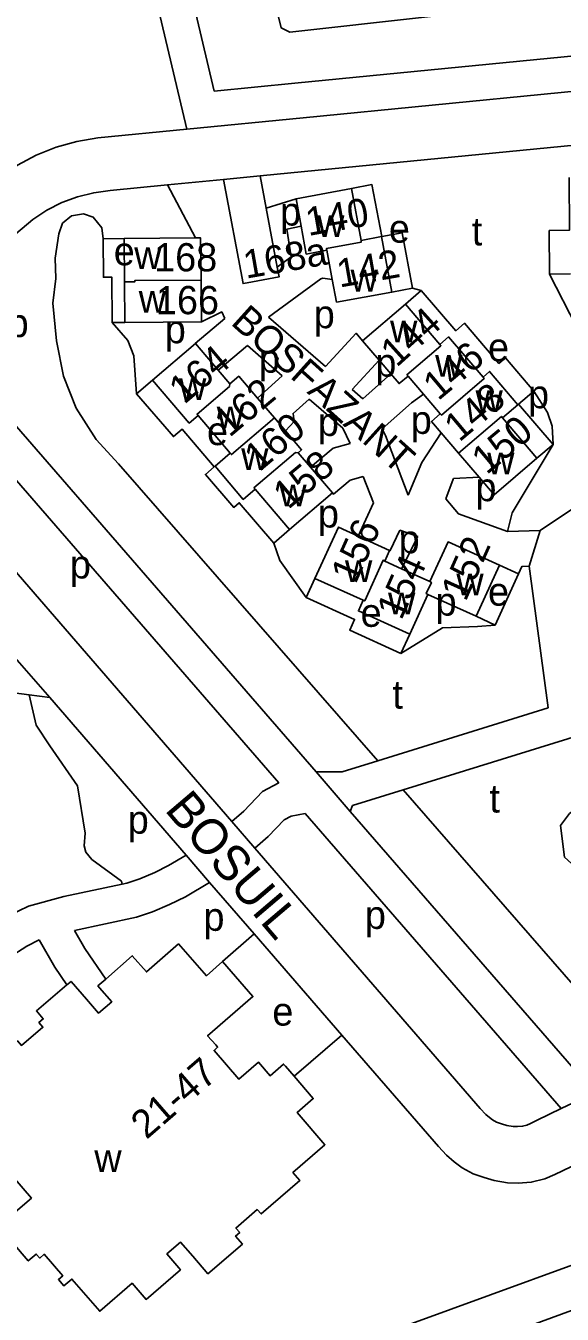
# Model space of a CAD drawing. Extents: x 155854 to 157362, y 383621 to 384685.
# Drawn here: x 156844.9 to 156920.8, y 383747.7 to 383930.2 of the extents above; entities that cross this region are included whole.
import ezdxf

# ---------------------------------------------------------------- set-up
doc = ezdxf.new("R2010")
doc.units = 0
for name, color, linetype in [('BLT_Basislijn', 7, 'Continuous'), ('BLT_Bebouwing', 7, 'Continuous'), ('BLT_Centroide', 7, 'Continuous'), ('BLT_Huisnummer', 7, 'Continuous'), ('BLT_Huisnummer_reeks', 7, 'Continuous'), ('BLT_Huisnummer_zonder_bebouwing', 7, 'Continuous'), ('BLT_Onderverdeling_panden', 7, 'Continuous'), ('BLT_Straatnaam', 7, 'Continuous'), ('BLT_Straatnaam_verkleind', 7, 'Continuous'), ('BLT_Vlakafsluiter', 7, 'Continuous')]:
    doc.layers.add(name, color=color, linetype=linetype)

msp = doc.modelspace()

# ---------------------------------------------------------------- linework, layer by layer
at = {"layer": 'BLT_Basislijn'}
for p, q in [((156831.19, 384070.4), (156867.7, 383915.55)), ((156928.32, 383913.85), (156878.09, 383908.93)), ((156878.09, 383908.93), (156872.9, 383908.43)), ((156878.94, 383904.37), (156878.09, 383908.93)), ((156864.96, 383907.65), (156856.85, 383906.85)), ((156872.9, 383908.43), (156864.96, 383907.65)), ((156864.96, 383907.65), (156868.93, 383900.13)), ((156883.16, 383905.7), (156878.94, 383904.37)), ((156880.5, 383896.02), (156878.94, 383904.37)), ((156838.28, 383896.36), (156845.93, 383902.77)), ((156858.82, 383900.05), (156855.86, 383900)), ((156919.04, 383895.02), (156922.01, 383895.04)), ((156919.04, 383895.02), (156922.86, 383887.56)), ((156896.7, 383892.48), (156899.63, 383893.03)), ((156900.88, 383892.69), (156898.62, 383890.76)), ((156899.63, 383893.03), (156900.88, 383892.69)), ((156885.98, 383824.5), (156829.83, 383889.28)), ((156879.25, 383888.91), (156887.3, 383881.93)), ((156857.15, 383888.14), (156858.92, 383888.16)), ((156880.7, 383822.96), (156826, 383886.06)), ((156872.14, 383881.4), (156876.27, 383884.88)), ((156876.27, 383884.88), (156881.2, 383880.6)), ((156891.08, 383878.65), (156894.92, 383882.81)), ((156862.86, 383879.99), (156860.6, 383878.06)), ((156881.2, 383880.6), (156877.68, 383877.46)), ((156892.59, 383877.34), (156896.58, 383880.87)), ((156891.08, 383878.65), (156892.59, 383877.34)), ((156917.25, 383868.95), (156919.52, 383870.89)), ((156931.24, 383867.82), (156917.68, 383858.68)), ((156892.67, 383866.36), (156894.11, 383862.61)), ((156894.11, 383862.61), (156891.93, 383857.91)), ((156880, 383856.92), (156882.24, 383858.83)), ((156897.84, 383858.76), (156900.41, 383857.83)), ((156900.41, 383857.83), (156898.1, 383853.28)), ((156913.08, 383858.54), (156917.68, 383858.68)), ((156911.35, 383845.3), (156914.64, 383852.55)), ((156914.64, 383852.55), (156911.93, 383853.78)), ((156916.12, 383853.63), (156918.83, 383833.56)), ((156885.83, 383851.91), (156884.6, 383849.21)), ((156908.63, 383846.54), (156911.35, 383845.3)), ((156898, 383841.29), (156899.24, 383844)), ((156843.37, 383840.73), (156848.31, 383835.02)), ((156848.31, 383835.02), (156845.38, 383835.41)), ((156848.31, 383835.02), (156867.61, 383812.7)), ((156918.83, 383833.56), (156894.71, 383826.06)), ((156936.17, 383833.7), (156898.3, 383821.94)), ((156874.06, 383817.46), (156877.33, 383813.68)), ((156920.69, 383776.82), (156884.46, 383818.62)), ((156925.36, 383779.07), (156890.83, 383818.91)), ((156867.61, 383812.7), (156870.93, 383808.85)), ((156870.93, 383808.85), (156877.24, 383801.56)), ((156872.76, 383797.63), (156877.24, 383801.56)), ((156877.24, 383801.56), (156889.62, 383787.23)), ((156889.62, 383787.23), (156882.88, 383781.38)), ((156920.69, 383776.82), (156925.36, 383779.07)), ((156786.01, 383698.59), (156938.36, 383754.12))]:
    msp.add_line(p, q, dxfattribs=at)
for points in [[(156861.58, 384009.03), (156851.38, 384006.57), (156871.56, 383920.95)], [(156957.23, 383937.68), (156882.29, 383929.3), (156881.04, 383929.91), (156864.57, 383996.87)], [(156959.19, 383929.54), (156882.96, 383922.07)], [(156957.18, 383924.32), (156884.17, 383917.17)], [(156882.96, 383922.07), (156871.56, 383920.95)], [(156884.17, 383917.17), (156867.7, 383915.55)], [(156841.22, 383908.74), (156843.72, 383910.43), (156846.39, 383911.85), (156849.22, 383912.99), (156852.13, 383913.81), (156855.1, 383914.32)], [(156867.7, 383915.55), (156855.1, 383914.32)], [(156921.79, 383908.72), (156921.85, 383901.22), (156918.99, 383901.19), (156919.04, 383895.02)], [(156845.93, 383902.77), (156847.89, 383904.07), (156850, 383905.14), (156852.23, 383905.97), (156854.53, 383906.55), (156856.85, 383906.85)], [(156872.9, 383908.43), (156875.65, 383893.67), (156876.25, 383893.78)], [(156899.63, 383893.03), (156898.17, 383900.87), (156895.28, 383900.33), (156893.9, 383907.69), (156890.99, 383907.14)], [(156894.71, 383826.06), (156858.02, 383868.14), (156854.85, 383871.57), (156852.03, 383876.04), (156850.25, 383880.56), (156849.27, 383885.57), (156848.76, 383890.92), (156849.14, 383894.37), (156849.08, 383897.28), (156849.57, 383900.72), (156850.12, 383902.21), (156851.4, 383903.29), (156853.08, 383903.56), (156854.46, 383903.06), (156855.67, 383901.55), (156855.86, 383900)], [(156880.5, 383896.02), (156882.45, 383897.44), (156881.86, 383901.39), (156883.88, 383901.79)], [(156855.86, 383900), (156855.9, 383894.57), (156857.1, 383894.58), (156857.15, 383888.14)], [(156876.25, 383893.78), (156880.76, 383894.62), (156880.5, 383896.02)], [(156879.25, 383888.91), (156886.67, 383894.33), (156886.94, 383894.43), (156888.27, 383894.23)], [(156916.81, 383878.43), (156912.79, 383883.14), (156911.87, 383882.36), (156907, 383888.05), (156905.75, 383886.98), (156900.88, 383892.69)], [(156868.91, 383885.17), (156868.89, 383885.2), (156873.06, 383888.72)], [(156869.76, 383888.25), (156872.63, 383889.66), (156873.06, 383888.72)], [(156857.15, 383888.14), (156859.37, 383885.6), (156860.22, 383883.42), (156860.6, 383878.06)], [(156887.3, 383881.93), (156891.65, 383886.63), (156892.56, 383885.56)], [(156821.72, 383882.48), (156821.08, 383881.75), (156820.87, 383880.9), (156820.96, 383879.8), (156821.2, 383879.05), (156821.71, 383878.01), (156874.06, 383817.46)], [(156860.6, 383878.06), (156865.79, 383871.99), (156867.03, 383873.06), (156871.59, 383867.73), (156870.33, 383866.65), (156874.34, 383861.96), (156875.12, 383862.62), (156880, 383856.92)], [(156895.35, 383873.1), (156899.49, 383876.78), (156901.21, 383877.99)], [(156919.52, 383870.89), (156914.65, 383876.58), (156916.81, 383878.43)], [(156916.81, 383878.43), (156918.76, 383875.4), (156919.41, 383873.46), (156919.52, 383870.89)], [(156885.01, 383877.3), (156882.73, 383875.27), (156882.9, 383874.12), (156881.65, 383872.82)], [(156885.01, 383877.3), (156889.77, 383873.17), (156890.79, 383871.03)], [(156895.35, 383873.1), (156895.8, 383872.16), (156899.04, 383863.71)], [(156903.71, 383872.53), (156900.94, 383868.32), (156899.04, 383863.71)], [(156885.2, 383867.66), (156888.4, 383870.34), (156890.79, 383871.03)], [(156919.52, 383870.89), (156913.75, 383861.22), (156913.08, 383858.54)], [(156888.31, 383864.02), (156888.44, 383863.86), (156890.79, 383865.83), (156892.67, 383866.36)], [(156909.06, 383866.26), (156905.45, 383866.07), (156905.38, 383865.97), (156904.34, 383863.17)], [(156904.34, 383863.17), (156906.13, 383861.07), (156913.08, 383858.54)], [(156897.84, 383858.76), (156896.48, 383855.84), (156896.39, 383855.88)], [(156880, 383856.92), (156880.88, 383854.44), (156884.6, 383849.21)], [(156914.64, 383852.55), (156915.12, 383853.6), (156916.12, 383853.63)], [(156884.6, 383849.21), (156891.43, 383846.1), (156890.75, 383844.6), (156898, 383841.29)], [(156898, 383841.29), (156903.9, 383844.9), (156908.85, 383845.11), (156911.35, 383845.3)], [(156845.38, 383835.41), (156841.75, 383835.9), (156838.64, 383834.71), (156835.29, 383832.88), (156833.68, 383831.74), (156832.77, 383830.76), (156832.07, 383829.68), (156831.53, 383828.4), (156830.87, 383825.24)], [(156845.38, 383835.41), (156846.38, 383831.13), (156848.3, 383828.2), (156852.25, 383822.51), (156853.3, 383815.83), (156853.19, 383814.02), (156853.41, 383813.15), (156854.25, 383812.11), (156858.47, 383809), (156858.55, 383808.6)], [(156894.71, 383826.06), (156889.66, 383824.5), (156885.98, 383824.5)], [(156880.7, 383822.96), (156878.39, 383821.72), (156875.76, 383818.95), (156874.06, 383817.46)], [(156898.3, 383821.94), (156891.15, 383819.72), (156890.83, 383818.91)], [(156930.33, 383797.53), (156933.42, 383786.63), (156933.49, 383785.67), (156933.02, 383784.82), (156931.88, 383784.36), (156930.72, 383784.77), (156898.3, 383821.94)], [(156929.31, 383821.54), (156927.43, 383821.08), (156924.6, 383820.45), (156921.87, 383818.62), (156920.58, 383816.92), (156921.16, 383812.41), (156924.11, 383809.75)], [(156884.46, 383818.62), (156882.47, 383818.23), (156881.46, 383817.7), (156879.23, 383815.34), (156877.33, 383813.68)], [(156877.33, 383813.68), (156909.22, 383776.8), (156909.99, 383775.99), (156910.51, 383775.53), (156910.95, 383775.22), (156911.53, 383774.9), (156912.25, 383774.64), (156912.96, 383774.43), (156913.88, 383774.28), (156914.47, 383774.26), (156915.2, 383774.31), (156915.79, 383774.45), (156916.35, 383774.69), (156917.27, 383775.17), (156920.69, 383776.82)], [(156867.61, 383812.7), (156865.11, 383811.22), (156863.17, 383810.26), (156861.03, 383809.36), (156859.22, 383808.74), (156858.55, 383808.6)], [(156858.55, 383808.6), (156850.29, 383806.84), (156845.28, 383805.5), (156842.57, 383804.17), (156839.65, 383802.25), (156835.82, 383799.25), (156833.13, 383796.74)], [(156870.93, 383808.85), (156867.49, 383806.82), (156865.25, 383805.71), (156862.82, 383804.69), (156860.56, 383803.91), (156851.79, 383802.05)], [(156856.22, 383795.15), (156853.26, 383799.48), (156851.79, 383802.05)], [(156846.81, 383800.69), (156845.06, 383799.82), (156842.57, 383798.19), (156839.07, 383795.45), (156836.66, 383793.19), (156835.33, 383791.78), (156834.65, 383790.76), (156834.1, 383789.4), (156832, 383781.21), (156831, 383778.9), (156829.4, 383776.88), (156827.71, 383774.94), (156826.92, 383773.54), (156826.78, 383773.08)], [(156850.73, 383794.32), (156849.02, 383796.82), (156846.81, 383800.69)], [(156889.62, 383787.23), (156903.29, 383771.42), (156904.45, 383770.21), (156905.54, 383769.26), (156906.68, 383768.44), (156908.22, 383767.59), (156909.76, 383767.03), (156911.17, 383766.62), (156913.07, 383766.3), (156914.6, 383766.25), (156916.44, 383766.37), (156918.35, 383766.84)], [(156918.35, 383766.84), (156919.78, 383767.46), (156920.85, 383768.01), (156926.12, 383770.56)], [(156797.74, 383709.25), (156933.44, 383758.72), (156934.4, 383759.51), (156934.72, 383760.23), (156934.34, 383761.07)]]:
    msp.add_lwpolyline(points, dxfattribs=at)
at = {"layer": 'BLT_Bebouwing'}
for p, q in [((156883.16, 383905.7), (156890.99, 383907.14)), ((156890.99, 383907.14), (156892.35, 383899.78)), ((156883.88, 383901.79), (156883.16, 383905.7)), ((156858.82, 383900.05), (156868.93, 383900.13)), ((156858.87, 383893.9), (156858.82, 383900.05)), ((156888.27, 383894.23), (156887.51, 383898.4)), ((156869.71, 383894.18), (156869.76, 383888.25)), ((156888.86, 383891.02), (156888.27, 383894.23)), ((156858.92, 383888.16), (156858.87, 383893.9)), ((156896.7, 383892.48), (156888.86, 383891.02)), ((156892.56, 383885.56), (156898.62, 383890.76)), ((156898.62, 383890.76), (156903.49, 383885.05)), ((156869.76, 383888.25), (156858.92, 383888.16)), ((156862.86, 383879.99), (156868.91, 383885.17)), ((156868.91, 383885.17), (156872.14, 383881.4)), ((156894.92, 383882.81), (156892.56, 383885.56)), ((156872.14, 383881.4), (156873.79, 383879.47)), ((156896.58, 383880.87), (156894.92, 383882.81)), ((156901.21, 383877.99), (156899, 383880.57)), ((156903.56, 383875.24), (156901.21, 383877.99)), ((156877.68, 383877.46), (156880.09, 383874.64)), ((156873.85, 383869.67), (156869.3, 383875)), ((156880.09, 383874.64), (156881.65, 383872.82)), ((156912.37, 383874.66), (156917.25, 383868.95)), ((156906.14, 383869.67), (156903.71, 383872.53)), ((156883.44, 383869.72), (156885.2, 383867.66)), ((156909.06, 383866.26), (156906.14, 383869.67)), ((156885.2, 383867.66), (156888.31, 383864.02)), ((156882.24, 383858.83), (156877.37, 383864.54)), ((156888.31, 383864.02), (156882.24, 383858.83)), ((156891.93, 383857.91), (156896.39, 383855.88)), ((156896.39, 383855.88), (156895.71, 383854.37)), ((156895.71, 383854.37), (156898.1, 383853.28)), ((156898.1, 383853.28), (156902.1, 383851.45)), ((156911.93, 383853.78), (156908.63, 383846.54)), ((156892.66, 383848.82), (156885.83, 383851.91)), ((156901.81, 383849.64), (156899.24, 383844)), ((156908.63, 383846.54), (156901.81, 383849.64))]:
    msp.add_line(p, q, dxfattribs=at)
for points in [[(156887.51, 383898.4), (156884.6, 383897.86), (156883.88, 383901.79)], [(156868.93, 383900.13), (156869.65, 383900.13), (156869.71, 383894.18)], [(156892.35, 383899.78), (156895.25, 383900.32), (156896.7, 383892.48)], [(156903.49, 383885.05), (156904.75, 383886.12), (156909.62, 383880.43)], [(156909.62, 383880.43), (156910.54, 383881.22), (156914.56, 383876.51), (156912.37, 383874.66)], [(156869.3, 383875), (156868.04, 383873.92), (156862.86, 383879.99)], [(156873.79, 383879.47), (156875.05, 383880.55), (156877.68, 383877.46)], [(156899, 383880.57), (156897.74, 383879.51), (156896.58, 383880.87)], [(156903.71, 383872.53), (156902.31, 383874.16), (156903.56, 383875.24)], [(156881.65, 383872.82), (156883.93, 383870.14), (156883.44, 383869.72)], [(156877.37, 383864.54), (156875.69, 383863.11), (156871.69, 383867.81), (156873.85, 383869.67)], [(156917.25, 383868.95), (156911.18, 383863.77), (156909.06, 383866.26)], [(156885.83, 383851.91), (156889.14, 383859.18), (156891.93, 383857.91)], [(156902.1, 383851.45), (156904.67, 383857.09), (156911.93, 383853.78)], [(156899.24, 383844), (156891.98, 383847.3), (156892.66, 383848.82)], [(156856.22, 383795.15), (156859.98, 383798.45), (156861.98, 383796.16), (156866.52, 383800.14), (156870.48, 383795.63), (156872.76, 383797.63)], [(156872.76, 383797.63), (156877.05, 383792.67), (156870.64, 383787.13), (156871.78, 383785.82), (156871.97, 383785.59), (156872.06, 383785.49), (156871.85, 383785.31), (156871.55, 383785.04), (156875.05, 383780.99), (156877.83, 383783.39), (156879.49, 383781.47), (156881.37, 383783.09), (156881.39, 383783.11), (156881.66, 383782.8), (156882.88, 383781.38)], [(156840.02, 383765.89), (156836.46, 383770), (156838.75, 383771.97), (156834.8, 383776.55), (156839.33, 383780.47), (156838.35, 383781.62), (156843.74, 383786.4), (156844.29, 383785.75), (156847.33, 383788.34), (156846.77, 383788.99), (156847.38, 383789.51), (156846.42, 383790.64), (156850.73, 383794.32)], [(156850.73, 383794.32), (156851.32, 383794.82), (156853.48, 383792.32), (156855.2, 383790.32), (156857.08, 383791.94), (156855.35, 383793.92), (156855.12, 383794.18), (156856.22, 383795.15)], [(156882.88, 383781.38), (156885.6, 383778.23), (156883.31, 383776.25), (156887.25, 383771.68), (156882.7, 383767.75), (156883.69, 383766.6), (156878.22, 383761.88), (156877.67, 383762.51), (156874.64, 383759.89), (156875.18, 383759.26), (156874.59, 383758.74), (156875.57, 383757.61), (156870.69, 383753.41), (156868.53, 383755.91), (156866.8, 383757.9), (156864.87, 383756.23), (156866.59, 383754.23), (156866.8, 383753.99), (156861.93, 383749.77), (156859.94, 383752.07), (156855.37, 383748.11), (156851.44, 383752.65), (156850.31, 383751.68), (156849.52, 383752.59), (156850.15, 383753.14), (156847.53, 383756.17), (156846.9, 383755.63), (156846.4, 383756.21), (156845.26, 383755.23), (156841.05, 383760.1)], [(156841.05, 383760.1), (156843.47, 383762.19), (156845.71, 383764.12), (156843.07, 383767.19), (156840.83, 383765.25), (156840.68, 383765.12), (156840.02, 383765.89)]]:
    msp.add_lwpolyline(points, dxfattribs=at)
at = {"layer": 'BLT_Onderverdeling_panden'}
for points in [[(156887.51, 383898.4), (156887.46, 383898.64), (156892.39, 383899.54), (156892.35, 383899.78)], [(156858.87, 383893.9), (156860.32, 383893.9), (156860.32, 383894.1), (156869.71, 383894.18)], [(156899, 383880.57), (156898.84, 383880.76), (156903.65, 383884.87), (156903.49, 383885.05)], [(156869.3, 383875), (156869.14, 383875.18), (156873.75, 383879.11), (156873.79, 383879.47)], [(156903.56, 383875.24), (156903.72, 383875.05), (156909.79, 383880.23), (156909.62, 383880.43)], [(156880.09, 383874.64), (156874.02, 383869.46), (156873.85, 383869.67)], [(156906.14, 383869.67), (156912.21, 383874.85), (156912.37, 383874.66)], [(156877.37, 383864.54), (156877.2, 383864.74), (156883.06, 383869.74), (156883.44, 383869.72)], [(156892.66, 383848.82), (156892.87, 383848.72), (156895.47, 383854.48), (156895.71, 383854.37)], [(156902.1, 383851.45), (156902.31, 383851.35), (156901.58, 383849.75), (156901.81, 383849.64)]]:
    msp.add_lwpolyline(points, dxfattribs=at)
at = {"layer": 'BLT_Vlakafsluiter'}
for p, q in [((156917.68, 383858.68), (156916.12, 383853.63)), ((156890.83, 383818.91), (156885.98, 383824.5))]:
    msp.add_line(p, q, dxfattribs=at)

# ---------------------------------------------------------------- texts
at = {"layer": 'BLT_Centroide'}
for s, p in [('p', (156880.89, 383901.89)), ('w', (156886.14, 383900.28)), ('e', (156896.29, 383899.47)), ('t', (156908.04, 383899.08)), ('e', (156857.36, 383896.26)), ('w', (156860.26, 383895.72)), ('w', (156890.87, 383892.55)), ('w', (156860.89, 383889.55)), ('p', (156885.66, 383887.35)), ('p', (156842.34, 383886.1)), ('p', (156864.58, 383885.22)), ('w', (156896.46, 383885.34)), ('e', (156910.32, 383882.66)), ('p', (156877.89, 383881.05)), ('p', (156894.38, 383880.48)), ('w', (156902.84, 383880.47)), ('w', (156866.6, 383877.18)), ('w', (156908.55, 383875.49)), ('p', (156915.98, 383876.01)), ('w', (156871.93, 383873.18)), ('e', (156870.55, 383870.79)), ('p', (156886.25, 383872.09)), ('p', (156899.39, 383872.38)), ('w', (156875.39, 383867.26)), ('w', (156910.2, 383866.66)), ('w', (156880.79, 383862.14)), ('p', (156908.54, 383862.85)), ('p', (156886.25, 383859.12)), ('p', (156897.67, 383855.47)), ('p', (156851.15, 383851.9)), ('w', (156890.08, 383851.39)), ('w', (156905.84, 383849.53)), ('e', (156910.32, 383848.05)), ('w', (156896.17, 383846.83)), ('p', (156902.9, 383846.64)), ('e', (156892.29, 383845.05)), ('t', (156896.78, 383833.46)), ('t', (156910.51, 383818.74)), ('p', (156859.34, 383815.75)), ('p', (156870.05, 383801.99)), ('p', (156892.89, 383802.26)), ('e', (156879.8, 383788.56)), ('w', (156854.61, 383767.82))]:
    msp.add_text(s, height=4, dxfattribs=at).set_placement(p)
at = {"layer": 'BLT_Huisnummer'}
for s, rotation, p in [('140', 9.9241, (156884.89, 383900.41)), ('168', 359.9241, (156863.07, 383895.41)), ('142', 9.9241, (156889.3, 383893.1)), ('166', 359.9241, (156863.32, 383889.34)), ('144', 41.9241, (156897.38, 383881.71)), ('146', 39.9241, (156903.26, 383876.98)), ('164', 39.9241, (156867.3, 383876.46)), ('162', 39.9241, (156873.73, 383871.79)), ('148', 39.9241, (156906.25, 383871.13)), ('160', 39.9241, (156877.95, 383866.92)), ('150', 39.9241, (156910.13, 383866.5)), ('158', 39.9241, (156882.04, 383861.59)), ('156', 65.9241, (156891.58, 383850.98)), ('152', 65.9241, (156907.15, 383848.51)), ('154', 65.9241, (156898.05, 383845.86))]:
    msp.add_text(s, height=4, rotation=rotation, dxfattribs=at).set_placement(p)
at = {"layer": 'BLT_Huisnummer_reeks'}
msp.add_text('21-47', height=4, rotation=40.9241, dxfattribs=at).set_placement((156861.98, 383772.34))
at = {"layer": 'BLT_Huisnummer_zonder_bebouwing'}
msp.add_text('168a', height=4, rotation=9.9241, dxfattribs=at).set_placement((156876.07, 383894.36))
at = {"layer": 'BLT_Straatnaam'}
msp.add_text('BOSUIL', height=5, rotation=310.4144, dxfattribs=at).set_placement((156864.45, 383819.09))
at = {"layer": 'BLT_Straatnaam_verkleind'}
msp.add_text('BOSFAZANT', height=4, rotation=318.0275, dxfattribs=at).set_placement((156873.77, 383887.99))

doc.saveas('drawing.dxf')
